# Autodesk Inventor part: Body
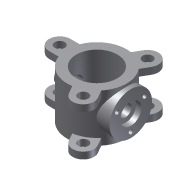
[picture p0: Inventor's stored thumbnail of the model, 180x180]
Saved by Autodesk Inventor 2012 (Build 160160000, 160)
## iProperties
Created: 2011-04
Part Number: Body
Material: Default
Document SubType Name: Modeling
Designer: Dell
Density: 1 g/cm^3
Author: Dell
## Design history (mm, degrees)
sketch "Sketch1"
  geometry: 1 further point
sketch "Sketch2"
  geometry: C1 r 97 at (0, 0); C2 r 140 at (0, 0); 1 further point
  constraints: 2 centre point, 1 coincident
  dimensions: "d0" = 194 diameter of C1; "d1" = 280 diameter of C2
extrude "Extrusion1" new body sketch "Sketch2" stored distance "d2" = 225; taper "d3" = 0 deg
workplane "Work Plane1"
sketch "Sketch3"
  geometry: L1 (-140, 112.5)-(140, 112.5) reference; C1 r 100 at (0, 0); 1 further point
  constraints: 1 centre point, 1 coincident
  dimensions: "d5" = 200 diameter of C1; "d7" = 112.5 distance from line of point (0, 0) L1 (derived)
extrude "Extrusion2" join sketch "Sketch3" stored distance "d8" = 225; taper "d9" = 0 deg
hole "Hole1" diameter "d12" = 56; stored, may be unused: countersink angle "d16" = 90 deg, drill point angle "d18" = 118 deg; dims "d13" = 6, "d14" = 100, "d15" = 25, "d17" = 428.75, "d39" = 10, "d40" = 10
workplane "Work Plane2"
sketch "Sketch4"
  geometry: C1 r 37.5 at (0, 0); C2 r 28 at (0, 0); 1 further point
  constraints: 2 centre point, 1 coincident
  dimensions: "d20" = 75 diameter of C1; "d37" = 56 diameter of C2
sketch "Sketch5"
  geometry: L1 (130.767, -50)-(175, -50); L2 (175, 50)-(130.767, 50); C1 r 23.5 at (175, 0); A1 r 50 centre (175, 0) between (175, -50) and (175, 50); A2 r 140 centre (0, 0) between (130.767, -50) and (130.767, 50); 1 further point
  constraints: 4 end point, 4 point on circle, 3 centre point, 2 coincident
  dimensions: "d29" = 50 radius of A1 (derived); "d30" = 47 diameter of C1 (derived); "d31" = 175 distance of A1.centre point (0, 0)
extrude "Extrusion4" join sketch "Sketch5" distance "d32" = 32; taper "d33" = 0 deg
pattern_circular "Circular Pattern1" dims angle "d35" = 360 deg
mirror "Mirror1"
extrude "Extrusion5" join sketch "Sketch4" stored distance "d38" = 32; taper "d41" = 0 deg
sketch "Sketch6"
  geometry: C1 r 50 at (0, 0); C2 r 100 at (0, 0); 3 further points
  constraints: 2 centre point, 4 other
  dimensions: "d44" = 75 distance of point (75, 0) C1.centre; "d45" = 360 deg dimension on C1.centre point (75, 0) (derived)
hole "Hole2" sketch "Sketch6" at (-37.5, 64.952) diameter "d46" = 20.3; stored, may be unused: countersink angle "d50" = 90 deg, drill point angle "d52" = 118 deg; dims "d47" = 6, "d48" = 4, "d49" = 2, "d51" = 15
pattern_circular "Circular Pattern2" dims angle "d54" = 360 deg
body "Solid1"
other parameters: "d19" = -325
